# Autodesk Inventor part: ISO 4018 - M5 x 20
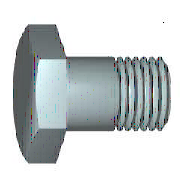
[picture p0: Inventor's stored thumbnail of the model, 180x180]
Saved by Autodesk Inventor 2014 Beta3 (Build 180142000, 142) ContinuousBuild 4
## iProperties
Created: 2011-11
Part Number: ISO 4018 - M5 x 20
Material: Steel
Description: Hexagon head screws. Product grade C
Document SubType Name: Modeling
Standard: ISO 4018
Designer: Thom Tremblay
Standard Revision: Third edition 1999-08-15
Standards Organization: ISO
Language: en-US
Size Designation: M5 x 20
Categories: <MemberInstance><Categories><Category DisplayName="Fasteners" InternalName="e4da775c-781d-43d5-af7c-5136215cf5a6" Mnemonic="FSTN"><Category DisplayName="Bolts"
Density: 7.85 g/cm^3
Appearance: Steel
IsCustomPart: 0
Author: Thom Tremblay
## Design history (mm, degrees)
node "WorkPlane1"
node "Sketch1"
node "WorkPoint1"
chamfer "Chamfer1" distance "d22" = 0.4 (= 0.5 x PTC); stored, may be unused: second distance "d23" = 0.4 (= 0.5 x PTC), angle "d39" = 45 deg
fillet "Fillet1" dims "d24" = 0.2 (= r)
node "MSC_A1"
node "MSC_PF1"
node "MSC_PT1"
body "Solid1"
sketch "Sketch2"
  geometry: L1 (-4, 2.309)-(-4, -2.309); L2 (0, 4.619)-(-4, 2.309); L3 (4, 2.309)-(0, 4.619); L4 (4, -2.309)-(4, 2.309); L5 (0, -4.619)-(4, -2.309); L6 (-4, -2.309)-(0, -4.619); C1 r 4 at (0, 0); 1 further point
  constraints: 12 end point, 6 tangent, 2 parallel, 2 vertical, 1 centre point
  dimensions: "d1" = 8 diameter of C1 (= ParS); "d29" = 0 distance of point (0, 0) C1.centre; "d30" = 0 distance of C1.centre point (0, 0)
extrude "Extrusion1" new body sketch "Sketch2" distance "d6" = 3.5 (= ParK); taper "d7" = 0 deg
revolve "Revolution1" stored, may be unused: angle "d14" = 360 deg
revolve "Revolution2" stored, may be unused: angle "d21" = 360 deg
thread "Thread1" dims "d32" = 0, "b" = 18.4 (= NLG - 2 x PTC)
sketch "Sketch3"
  geometry: L1 (4, 3.5)-(4.719, 3.5); L2 (4.719, 3.085)-(4, 3.5); L3 (4.719, 3.5)-(4.719, 3.085); L4 (0, -0.7)-(0, 4.2) reference; L5 (4.619, 0)-(4.619, 3.5) reference
  constraints: 6 end point, 1 horizontal, 1 vertical
  dimensions: "d25" = 0.1 distance between parallel lines of L5 L3; "d26" = 0 distance from line of L5.end L1; "d27" = 60 deg angle of L3 L2; "d28" = 4 distance from line of L4 L1.start (= 0.5 x ParS)
sketch "Sketch4"
  geometry: L1 (0, -20)-(0, 0); L2 (-2.5, -20)-(0, -20); L3 (-2.5, 0)-(-2.5, -20); L4 (0, 0)-(-2.5, 0); L5 (0, -20)-(0, 0); L6 (-3, 0)-(0.5, 0) reference; L7 (0, -24)-(0, 4) reference
  constraints: 10 end point, 2 horizontal, 2 vertical
  dimensions: "d18" = 2.5 distance of L1.start L2.start (= 0.5 x NND); "d20" = 20 distance of L3.start L2.start (= NLG); "d33" = 0 distance between parallel lines of L7 L1; "d34" = 0 distance between parallel lines of L6 L4
other parameters: "NND" = 5 [user parameter; used in 2 equation terms], "NLG" = 20 [user parameter; used in 2 equation terms], "PTC" = 0.8 [user parameter; used in 3 equation terms], "ParK" = 3.5 [user parameter; used in 1 equation term], "ParS" = 8 [user parameter; used in 3 equation terms], "msp_es" = 4.61894 (= 0.577367 x ParS) [user parameter], "r" = 0.2 [user parameter; used in 1 equation term], "d2" = 15 (derived), "d4" = 17.32102 (derived), "d8" = 15 (derived), "d10" = 0 (derived), "d12" = 30 deg (derived), "d15" = 0 (derived), "d37" = 0, "d38" = 0, "d40" = 0, "d41" = 0, "d42" = 0, "THREADDIA" = 5 (= NND) [user parameter]
